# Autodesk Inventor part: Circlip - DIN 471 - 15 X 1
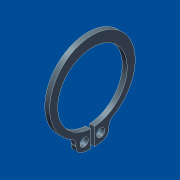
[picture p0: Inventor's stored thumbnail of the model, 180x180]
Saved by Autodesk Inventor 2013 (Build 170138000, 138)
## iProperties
Shininess: 41.0
Length Units: 11269
Angle Units: 11279
Time Units: 11290
Mass Units: 11283
Length Display Precision: 3
Angle Display Precision: 2
Created: 2001-06
Part Number: Circlip - DIN 471 - 15 X 1
Material: Standard
Document SubType Name: Modellieren
Designer: Administrator
Density: 1 g/cm^3
Density: 0.0
Volumn: 0.0
Area: 0.0
PropertySet Name: Model Information
Control State: 0
Master: False
Checked Out: False
Author: Administrator
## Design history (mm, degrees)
body "Solid1"
feature "Basis1"
